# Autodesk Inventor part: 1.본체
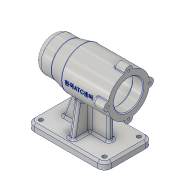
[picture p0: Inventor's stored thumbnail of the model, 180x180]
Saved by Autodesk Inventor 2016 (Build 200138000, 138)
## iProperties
Created: 2019-07
Part Number: 1.본체
Material: 알루미늄 6061
Document SubType Name: Modeling
Designer: 605-11
Density: 2.7 g/cm^3
Appearance: 알루미늄 - 평지
Mass: 644.389 g
Surface Area: 654.079 cm^2
Volume: 238.663 cm^3
Author: 605-11
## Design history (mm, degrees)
sketch "스케치1"
  geometry: L1 (-56, 0)-(56, 0); L2 (56, 21)-(41, 21); L3 (41, 21)-(41, 24); L4 (41, 24)-(-13, 24); L5 (-13, 24)-(-13, 21); L6 (-13, 21)-(-25, 21); L7 (-25, 21)-(-25, 17.5); L8 (-25, 17.5)-(-43, 17.5); L9 (-43, 17.5)-(-43, 16); L10 (-43, 16)-(-47, 16); L11 (-47, 16)-(-47, 10.5); L12 (-47, 10.5)-(-50, 10.5); L13 (-50, 10.5)-(-50, 0); L14 (-56, 0)-(-56, 25); L15 (-56, 25)-(-31, 25); L16 (-31, 25)-(-11, 30); L17 (-11, 30)-(56, 30); L18 (56, 30)-(56, 21); 1 further point
  constraints: 36 end point, 13 perpendicular, 3 horizontal, 1 midpoint, 1 point on line, 1 vertical, 1 vertical alignment
  dimensions: "d0" = 112 distance of L1.start L1.end; "d1" = 56 distance of point (0, 0) L1.start (= 0.5 x d0); "d2" = 15 distance of L2.start L2.end; "d3" = 54 distance of L3.end L4.end; "d4" = 12 distance of L5.end L6.end; "d5" = 18 distance of L7.end L8.end; "d6" = 4 distance of L9.end L10.end; "d7" = 3 distance of L11.end L12.end; "d9" = 25 distance of L14.end L15.end; "d10" = 45 horizontal distance of L16.end L14.end; "d11" = 42 diameter of L2 L1; "d12" = 21 diameter of L12 L1; "d13" = 32 diameter of L10 L1; "d14" = 35 diameter of L8 L1; "d15" = 50 diameter of L15 L1; "d17" = 42 diameter of L6 L1; "d18" = 48 diameter of L4 L1; "d21" = 60 diameter of L17 L1
revolve "회전1" sketch "스케치1" stored, may be unused: angle "d22" = 90 deg
node "작업 평면1"
sketch "스케치2"
  geometry: L1 (56, -35)-(-56, -35); L2 (-56, -35)-(-56, 35); L3 (-56, 35)-(56, 35); L4 (56, 35)-(56, -35); 3 further points
  constraints: 8 end point, 2 midpoint, 2 parallel, 1 horizontal, 1 horizontal alignment, 1 perpendicular, 1 vertical alignment
  dimensions: "d24" = 112 distance of L2.end L3.end; "d25" = 70 distance of L1.end L2.end
extrude "돌출1" join sketch "스케치2" distance "d26" = 10; taper "d27" = 0 deg
fillet "모깎기1" dims "d28" = 10
sketch "스케치3"
  geometry: L1 (46, -70)-(-46, -70) reference; L2 (-56, -70)-(-46, -70) reference; L3 (46, -70)-(56, -70) reference; L4 (-11, -30)-(56, -30) reference; L5 (-31, -25)-(-11, -30) reference; L6 (-36, -70)-(-20.074, -26.243); L7 (31, -70)-(31, -26.243); L8 (-56, -80)-(-56, -70) reference; L9 (-20.074, -26.243)-(31, -26.243); L10 (-36, -70)-(31, -70); 1 further point
  constraints: 8 end point, 2 point on line, 1 collinear, 1 horizontal, 1 perpendicular
  dimensions: "d29" = 25 distance of L3.end L7.start; "d30" = 20 distance from line of L8 L6.start; "d31" = 110 deg angle of L6 L1; "d32" = 51.07373 distance of L6.end L7.end
extrude "돌출2" join sketch "스케치3" stored distance "d33" = 8; taper "d34" = 0 deg
sketch "스케치4"
  geometry: L1 (-27.341, 4)-(-29.732, 4) reference; L2 (-29.732, -4)-(-27.341, -4) reference; L3 (-70, -25)-(-70, -35) reference; L4 (-70, -25)-(-70, 25) reference; L5 (-70, 35)-(-70, 25) reference; L6 (-70, -28)-(-22.666, -19.654); C1 r 25 at (0, 0) reference; A1 r 30 centre (0, 0) between (-29.732, -4) and (-29.732, 4) reference; A2 r 30 centre (0, 0) between (-29.732, -4) and (-29.732, 4) reference; 2 further points; 1 other entity
  constraints: 2 end point, 1 point on circle, 1 point on line, 1 other
  dimensions: "d35" = 7 distance of L3.end L6.start; "d36" = 100 deg angle of L3 L6
feature "리브1" sketch "스케치4" dims "d37" = 1, "d38" = 8, "d39" = 0, "d40" = 0, "d41" = 1, "d42" = 1
sketch "스케치5"
  geometry: A1 r 30 centre (0, 0) between (4, -29.732) and (-4, -29.732) reference; A2 r 30 centre (0, 0) between (4, -29.732) and (-4, -29.732) reference; A3 r 6 centre (0, 30) between (5.97, 29.4) and (-5.97, 29.4); 1 further point
  constraints: 5 point on circle, 1 centre point, 1 vertical alignment
  dimensions: "d43" = 60 diameter of A1 (derived); "d45" = 6 radius of A3
extrude "돌출3" join sketch "스케치5" distance "d46" = 16; taper "d47" = 0 deg
sketch "스케치6"
  geometry: A1 r 6 centre (0, 0) between (5.97, -0.6) and (-5.97, -0.6) reference; 1 further point
hole "구멍1" sketch "스케치6" at (0, 0) diameter "d48" = 3.242; stored, may be unused: countersink angle "d52" = 90 deg, drill point angle "d54" = 120 deg; dims "d49" = 8, "d50" = 4, "d51" = 2, "d53" = 11
sketch "스케치7"
  geometry: C1 r 3 at (-46, 25); A1 r 10 centre (-46, 25) between (-46, 35) and (-56, 25) reference; A2 r 10 centre (46, 25) between (56, 25) and (46, 35) reference; A3 r 10 centre (46, -25) between (46, -35) and (56, -25) reference; A4 r 10 centre (-46, -25) between (-56, -25) and (-46, -35) reference; 1 further point
  constraints: 1 centre point, 1 coincident
  dimensions: "d58" = 6 diameter of C1; "d59" = 92 distance of A2.centre A1.centre (derived); "d60" = 50 distance of A4.centre A1.centre (derived)
extrude "돌출4" cut sketch "스케치7" stored distance "d61" = 16; taper "d62" = 0 deg
chamfer "모따기1" distance "d69" = 3; stored, may be unused: second distance "d70" = 2, angle "d71" = 45 deg
chamfer "모따기2" distance "d72" = 1; stored, may be unused: second distance "d73" = 2, angle "d74" = 45 deg
fillet "모깎기2" dims "d75" = 3
fillet "모깎기3" dims "d76" = 0.3
fillet "모깎기4" dims "d77" = 10
fillet "모깎기5" dims "d78" = 3
fillet "모깎기6" dims "d79" = 1
fillet "모깎기7" dims "d80" = 3
fillet "모깎기8" dims "d81" = 1
fillet "모깎기9" dims "d82" = 3
fillet "모깎기10" dims "d83" = 1
fillet "모깎기11" dims "d84" = 3
fillet "모깎기12" dims "d85" = 3
fillet "모깎기13" dims "d86" = 3
fillet "모깎기14" dims "d87" = 3
node "작업 평면2"
sketch "스케치8"
  geometry: L1 (33.5, 30.171)-(33.5, 36) reference; 2 further points
  constraints: 1 horizontal alignment, 1 other
  dimensions: "d88" = 42 distance from line of L1 point (-8.5, 0)
feature "엠보싱1" sketch "스케치8" dims "d0" = 112, "d89" = 0.5, "d90" = 0
node "솔리드1"
mirror "대칭1"
pattern_circular "원형 패턴1" dims angle "d56" = 360 deg
pattern_linear "직사각형 패턴1" dims "d65" = 92 (= d59)
node "투영된 루프1"
